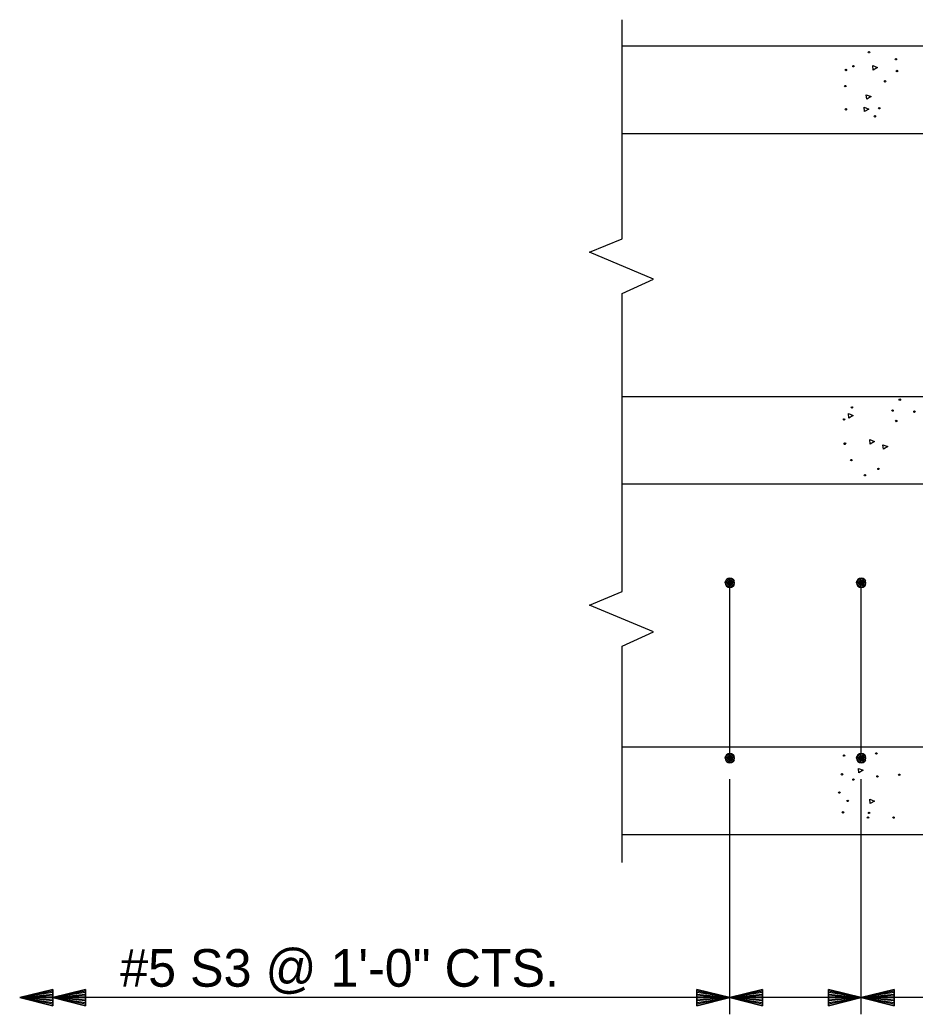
# Model space of a CAD drawing. Extents: x 0 to 177, y -1 to 127.
# Drawn here: x 164.731 to 168.137, y 68.407 to 72.189 of the extents above; entities that cross this region are included whole.
import ezdxf

# ---------------------------------------------------------------- set-up
doc = ezdxf.new("R2010")
doc.units = 0
for name, color, linetype in [('Dimension Lines', 7, 'Continuous'), ('Rebar Lines', 7, 'Continuous'), ('Sup Concrete Girder Lines', 7, 'Continuous'), ('Text', 7, 'Continuous')]:
    doc.layers.add(name, color=color, linetype=linetype)

msp = doc.modelspace()

# ---------------------------------------------------------------- linework, layer by layer
at = {"layer": 'Dimension Lines'}
for p, q in [((167.4318, 68.4071), (167.4318, 69.3008)), ((167.9318, 68.4071), (167.9318, 69.3008)), ((167.4318, 68.4702), (164.7309, 68.4702)), ((167.9318, 68.4702), (167.4318, 68.4702)), ((171.4318, 68.4702), (167.9318, 68.4702))]:
    msp.add_line(p, q, dxfattribs=at)
for points in [[(164.8559, 68.4702), (164.8559, 68.4764), (164.7309, 68.4702), (164.8559, 68.4827), (164.8559, 68.4889), (164.7309, 68.4702), (164.8559, 68.4952), (164.8559, 68.5014), (164.7309, 68.4702), (164.8559, 68.4389), (164.8559, 68.4452), (164.7309, 68.4702), (164.8559, 68.4514), (164.8559, 68.4577), (164.7309, 68.4702), (164.8559, 68.4639), (164.8559, 68.5014), (164.8559, 68.4389), (164.7309, 68.4702), (164.8559, 68.5014)], [(164.9809, 68.4702), (164.9809, 68.4764), (164.8559, 68.4702), (164.9809, 68.4827), (164.9809, 68.4889), (164.8559, 68.4702), (164.9809, 68.4952), (164.9809, 68.5014), (164.8559, 68.4702), (164.9809, 68.4389), (164.9809, 68.4452), (164.8559, 68.4702), (164.9809, 68.4514), (164.9809, 68.4577), (164.8559, 68.4702), (164.9809, 68.4639), (164.9809, 68.5014), (164.9809, 68.4389), (164.8559, 68.4702), (164.9809, 68.5014)], [(167.3068, 68.4702), (167.3068, 68.4639), (167.4318, 68.4702), (167.3068, 68.4577), (167.3068, 68.4514), (167.4318, 68.4702), (167.3068, 68.4452), (167.3068, 68.4389), (167.4318, 68.4702), (167.3068, 68.5014), (167.3068, 68.4952), (167.4318, 68.4702), (167.3068, 68.4889), (167.3068, 68.4827), (167.4318, 68.4702), (167.3068, 68.4764), (167.3068, 68.4389), (167.3068, 68.5014), (167.4318, 68.4702), (167.3068, 68.4389)], [(167.5568, 68.4702), (167.5568, 68.4764), (167.4318, 68.4702), (167.5568, 68.4827), (167.5568, 68.4889), (167.4318, 68.4702), (167.5568, 68.4952), (167.5568, 68.5014), (167.4318, 68.4702), (167.5568, 68.4389), (167.5568, 68.4452), (167.4318, 68.4702), (167.5568, 68.4514), (167.5568, 68.4577), (167.4318, 68.4702), (167.5568, 68.4639), (167.5568, 68.5014), (167.5568, 68.4389), (167.4318, 68.4702), (167.5568, 68.5014)], [(167.8068, 68.4702), (167.8068, 68.4639), (167.9318, 68.4702), (167.8068, 68.4577), (167.8068, 68.4514), (167.9318, 68.4702), (167.8068, 68.4452), (167.8068, 68.4389), (167.9318, 68.4702), (167.8068, 68.5014), (167.8068, 68.4952), (167.9318, 68.4702), (167.8068, 68.4889), (167.8068, 68.4827), (167.9318, 68.4702), (167.8068, 68.4764), (167.8068, 68.4389), (167.8068, 68.5014), (167.9318, 68.4702), (167.8068, 68.4389)], [(168.0568, 68.4702), (168.0568, 68.4764), (167.9318, 68.4702), (168.0568, 68.4827), (168.0568, 68.4889), (167.9318, 68.4702), (168.0568, 68.4952), (168.0568, 68.5014), (167.9318, 68.4702), (168.0568, 68.4389), (168.0568, 68.4452), (167.9318, 68.4702), (168.0568, 68.4514), (168.0568, 68.4577), (167.9318, 68.4702), (168.0568, 68.4639), (168.0568, 68.5014), (168.0568, 68.4389), (167.9318, 68.4702), (168.0568, 68.5014)]]:
    msp.add_lwpolyline(points, dxfattribs=at)
at = {"layer": 'Rebar Lines'}
for p, q in [((167.4318, 69.3809), (167.4318, 70.0476)), ((167.9318, 69.3809), (167.9318, 70.0476))]:
    msp.add_line(p, q, dxfattribs=at)
for points in [[(167.4495, 70.0476), (167.4481, 70.0543), (167.4443, 70.06), (167.4386, 70.0639), (167.4318, 70.0652), (167.4251, 70.0639), (167.4194, 70.06), (167.4156, 70.0544), (167.4142, 70.0476), (167.4156, 70.0409), (167.4194, 70.0352), (167.4251, 70.0313), (167.4318, 70.0299), (167.4386, 70.0313), (167.4443, 70.0351), (167.4481, 70.0408), (167.4495, 70.0476), (167.4318, 70.0476), (167.4142, 70.0476), (167.4156, 70.0544), (167.4318, 70.0476), (167.4194, 70.06), (167.4251, 70.0639), (167.4318, 70.0476), (167.4318, 70.0652), (167.4386, 70.0639), (167.4318, 70.0476), (167.4443, 70.06), (167.4481, 70.0543), (167.4318, 70.0476), (167.4481, 70.0408), (167.4443, 70.0351), (167.4318, 70.0476), (167.4386, 70.0313), (167.4318, 70.0299), (167.4318, 70.0476), (167.4251, 70.0313), (167.4194, 70.0352), (167.4318, 70.0476), (167.4156, 70.0409)], [(167.9495, 70.0476), (167.9481, 70.0543), (167.9443, 70.06), (167.9386, 70.0639), (167.9318, 70.0652), (167.9251, 70.0639), (167.9194, 70.06), (167.9156, 70.0544), (167.9142, 70.0476), (167.9156, 70.0409), (167.9194, 70.0352), (167.9251, 70.0313), (167.9318, 70.0299), (167.9386, 70.0313), (167.9443, 70.0351), (167.9481, 70.0408), (167.9495, 70.0476), (167.9318, 70.0476), (167.9142, 70.0476), (167.9156, 70.0544), (167.9318, 70.0476), (167.9194, 70.06), (167.9251, 70.0639), (167.9318, 70.0476), (167.9318, 70.0652), (167.9386, 70.0639), (167.9318, 70.0476), (167.9443, 70.06), (167.9481, 70.0543), (167.9318, 70.0476), (167.9481, 70.0408), (167.9443, 70.0351), (167.9318, 70.0476), (167.9386, 70.0313), (167.9318, 70.0299), (167.9318, 70.0476), (167.9251, 70.0313), (167.9194, 70.0352), (167.9318, 70.0476), (167.9156, 70.0409)], [(167.4495, 69.3809), (167.4481, 69.3877), (167.4443, 69.3934), (167.4386, 69.3972), (167.4318, 69.3985), (167.4251, 69.3972), (167.4194, 69.3934), (167.4156, 69.3877), (167.4142, 69.3809), (167.4156, 69.3742), (167.4194, 69.3685), (167.4251, 69.3646), (167.4318, 69.3633), (167.4386, 69.3646), (167.4443, 69.3684), (167.4481, 69.3742), (167.4495, 69.3809), (167.4318, 69.3809), (167.4142, 69.3809), (167.4156, 69.3877), (167.4318, 69.3809), (167.4194, 69.3934), (167.4251, 69.3972), (167.4318, 69.3809), (167.4318, 69.3985), (167.4386, 69.3972), (167.4318, 69.3809), (167.4443, 69.3934), (167.4481, 69.3877), (167.4318, 69.3809), (167.4481, 69.3742), (167.4443, 69.3684), (167.4318, 69.3809), (167.4386, 69.3646), (167.4318, 69.3633), (167.4318, 69.3809), (167.4251, 69.3646), (167.4194, 69.3685), (167.4318, 69.3809), (167.4156, 69.3742)], [(167.9495, 69.3809), (167.9481, 69.3877), (167.9443, 69.3934), (167.9386, 69.3972), (167.9318, 69.3985), (167.9251, 69.3972), (167.9194, 69.3934), (167.9156, 69.3877), (167.9142, 69.3809), (167.9156, 69.3742), (167.9194, 69.3685), (167.9251, 69.3646), (167.9318, 69.3633), (167.9386, 69.3646), (167.9443, 69.3684), (167.9481, 69.3742), (167.9495, 69.3809), (167.9318, 69.3809), (167.9142, 69.3809), (167.9156, 69.3877), (167.9318, 69.3809), (167.9194, 69.3934), (167.9251, 69.3972), (167.9318, 69.3809), (167.9318, 69.3985), (167.9386, 69.3972), (167.9318, 69.3809), (167.9443, 69.3934), (167.9481, 69.3877), (167.9318, 69.3809), (167.9481, 69.3742), (167.9443, 69.3684), (167.9318, 69.3809), (167.9386, 69.3646), (167.9318, 69.3633), (167.9318, 69.3809), (167.9251, 69.3646), (167.9194, 69.3685), (167.9318, 69.3809), (167.9156, 69.3742)]]:
    msp.add_lwpolyline(points, dxfattribs=at)
at = {"layer": 'Sup Concrete Girder Lines'}
for p, q in [((172.5785, 72.0893), (167.0228, 72.0893)), ((168.849, 71.7559), (167.0228, 71.7559)), ((168.849, 70.7559), (167.0228, 70.7559)), ((168.549, 70.4226), (167.0228, 70.4226)), ((168.549, 69.4226), (167.0228, 69.4226)), ((171.549, 69.0893), (167.0228, 69.0893))]:
    msp.add_line(p, q, dxfattribs=at)
for points in [[(167.0228, 70.1024), (167.0228, 71.1484), (167.142, 71.2031), (166.8978, 71.3052), (167.0228, 71.3567), (167.0228, 72.1892)], [(167.9772, 71.9979), (167.9758, 72.0151), (167.9937, 72.008), (167.9772, 71.9979)], [(167.9526, 71.8872), (167.9512, 71.9045), (167.9691, 71.8973), (167.9526, 71.8872)], [(167.9444, 71.8401), (167.9429, 71.8573), (167.9609, 71.8502), (167.9444, 71.8401)], [(167.8851, 70.6746), (167.8837, 70.6918), (167.9016, 70.6847), (167.8851, 70.6746)], [(167.9664, 70.5755), (167.965, 70.5927), (167.9829, 70.5856), (167.9664, 70.5755)], [(168.016, 70.5557), (168.0145, 70.5729), (168.0325, 70.5658), (168.016, 70.5557)], [(167.0228, 68.9833), (167.0228, 69.8066), (167.142, 69.8613), (166.8978, 69.9634), (167.0228, 70.0149), (167.0228, 70.1024)], [(167.9228, 69.3246), (167.9213, 69.3419), (167.9393, 69.3347), (167.9228, 69.3246)], [(167.9664, 69.2077), (167.965, 69.2249), (167.9829, 69.2178), (167.9664, 69.2077)]]:
    msp.add_lwpolyline(points, dxfattribs=at)
for centre in [(167.9613, 72.0663), (167.902, 72.013), (168.0638, 72.0396), (167.8733, 71.9987), (168.0679, 71.9946), (167.8712, 71.9372), (168.0228, 71.9556), (167.8733, 71.8491), (167.9839, 71.8224), (168.0003, 71.8532), (168.0787, 70.7446), (167.8963, 70.7149), (168.0509, 70.703), (168.1341, 70.699), (167.8665, 70.6693), (168.0648, 70.6634), (167.8685, 70.5761), (167.8705, 70.5781), (167.8943, 70.5147), (167.9974, 70.481), (167.9459, 70.4572), (167.9895, 69.3986), (167.8665, 69.3907), (167.8586, 69.3194), (167.9022, 69.2995), (167.9934, 69.3114), (168.0767, 69.3174), (167.8487, 69.25), (167.8804, 69.2183), (167.8626, 69.1746), (167.9617, 69.1726), (167.9577, 69.1548), (168.0549, 69.1548)]:
    msp.add_circle(centre, 0.00273, dxfattribs=at)

# ---------------------------------------------------------------- texts
at = {"layer": 'Text'}
msp.add_text('#5 S3 @ 1\'-0" CTS.', height=0.143021, dxfattribs=at).set_placement((165.1124, 68.5113))

doc.saveas('drawing.dxf')
